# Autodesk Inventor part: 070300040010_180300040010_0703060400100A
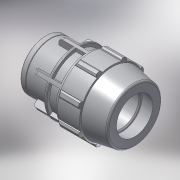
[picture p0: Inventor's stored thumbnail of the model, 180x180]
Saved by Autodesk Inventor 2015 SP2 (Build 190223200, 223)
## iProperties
Created: 2017-02
Part Number: 070300040010_180300040010_0703060400100A
Material: PVC-Piping
Description: PLASSON FEMALE ADAPTOR 40-1"
Document SubType Name: Modeling
Designer: KIM
Mass: 92.6774 g
Surface Area: 199.44 cm^2
Volume: 66.1981 cm^3
Density: 1.4 g/cm^3
Appearance: Smooth - White
Author: KIM
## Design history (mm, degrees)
derived "07030.ipt"
feature "Solid1::07030.ipt"
tag "TaggingFeature1"
body "Solid1"
other parameters: "d4" = 16, "d5" = 28, "d7" = 82, "d9" = 16, "d11" = 3.2, "d12" = 65.6, "d13" = 120 deg, "d15" = 10 deg, "d16" = 73.8, "d18" = 2, "d19" = 35 deg, "d20" = 17.5 deg, "d21" = 76.26, "d23" = 0, "d25" = 360 deg, "d27" = 1.64, "d34" = 4.1, "d35" = 33.6, "d36" = 0, "d42" = 28, "d43" = 2.46, "d46" = 1.2, "d49" = 84, "d51" = 112, "d53" = 0.8, "d55" = 360 deg, "d61" = 21, "d62" = 32, "d63" = 30.291, "d64" = 37.33333, "d65" = 4.1, "d66" = 0.5, "d67" = 1, "d68" = 6.3, "d69" = 59.04, "d70" = 2.05, "E_" = 82, "H_" = 112, "l_" = 84, "l_2" = 21, "Rp_" = 30.291
